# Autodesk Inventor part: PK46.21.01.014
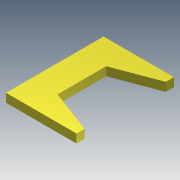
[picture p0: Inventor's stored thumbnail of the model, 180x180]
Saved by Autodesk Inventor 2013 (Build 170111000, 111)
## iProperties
Created: 2005-03
Part Number: PK46.21.01.014
Material: Steel, Mild
Document SubType Name: Modeling
Designer: salex
Manufacturer: Standard
Standards Organization: Custom
Density: 7.86 g/cm^3
Author: salex
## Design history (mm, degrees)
sketch "Эскиз1"
  geometry: L1 (0, 0)-(130, 0); L2 (130, 0)-(130, 15); L3 (130, 15)-(50, 45); L4 (50, 45)-(50, 135); L5 (50, 135)-(130, 165); L6 (130, 165)-(130, 180); L7 (130, 180)-(0, 180); L8 (0, 180)-(0, 0)
  constraints: 16 end point, 3 parallel, 2 collinear, 2 equal length, 1 horizontal, 1 perpendicular, 1 other
  dimensions: "d0" = 180 distance of L7.end L1.start; "d1" = 15 distance of L5.end L6.end; "d2" = 130 distance of L6.end L7.end; "d3" = 50 distance between parallel lines of L8 L4; "d4" = 45 distance from line of L1 L3.end
extrude "Выдавливание1" new body sketch "Эскиз1" distance "d5" = 16; taper "d6" = 0 deg
body "Solid1"
